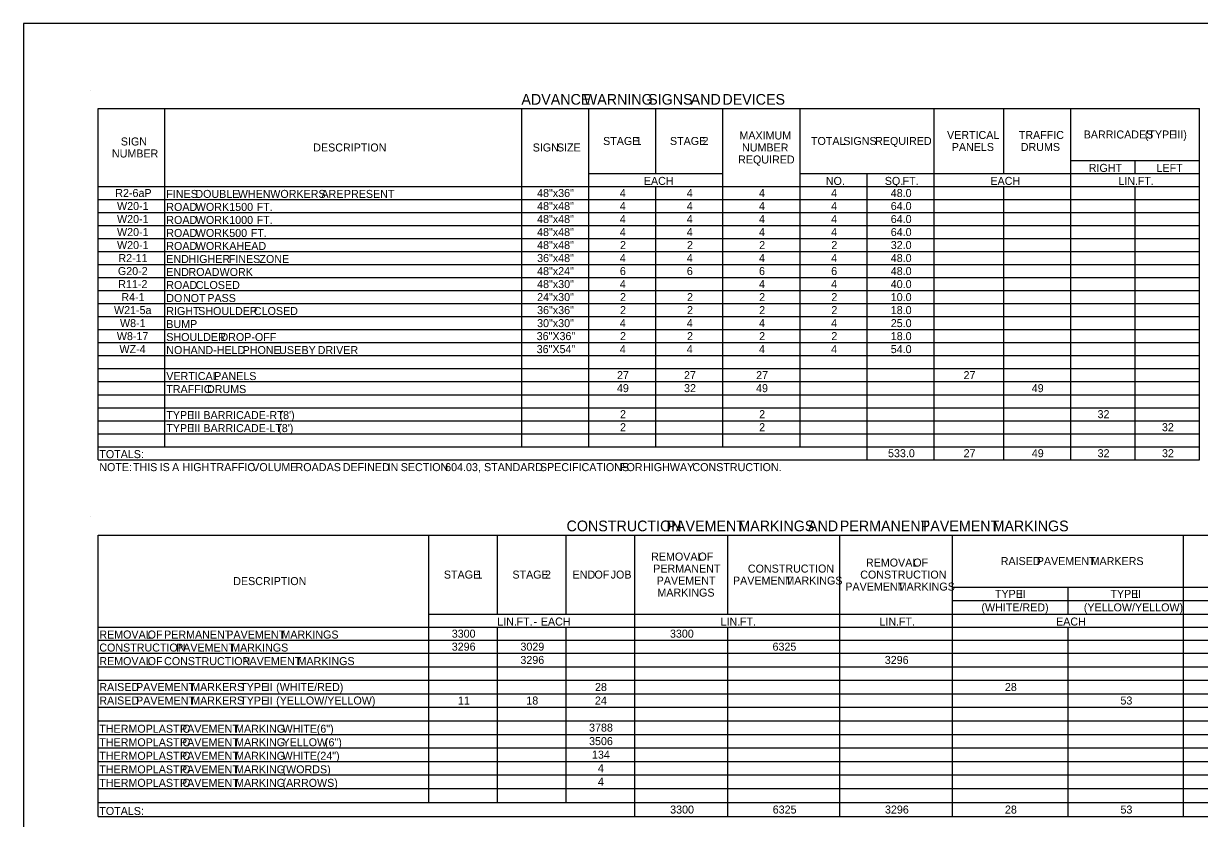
# Model space of a CAD drawing. Extents: x 3289 to 10164, y -1238 to -188.
# Drawn here: x 3289 to 4170, y -784 to -188 of the extents above; entities that cross this region are included whole.
import ezdxf

# ---------------------------------------------------------------- set-up
doc = ezdxf.new("R2010")
doc.units = 0
for name, color, linetype in [('Default', 7, 'Continuous'), ('DSN_DRFT_Named-Boundary', 7, 'Continuous'), ('DSN_QNTY_Annotation', 7, 'Continuous')]:
    doc.layers.add(name, color=color, linetype=linetype)

msp = doc.modelspace()

# ---------------------------------------------------------------- linework, layer by layer
at = {"layer": 'DSN_DRFT_Named-Boundary'}
for p, q in [((3338.57, -237.74), (3338.57, -237.74)), ((3338.57, -557.44), (3338.57, -557.44))]:
    msp.add_line(p, q, dxfattribs=at)
msp.add_lwpolyline([(3288.57, -1237.74), (4913.57, -1237.74), (4913.57, -187.74), (3288.57, -187.74)], close=True, dxfattribs=at)
at = {"layer": 'DSN_QNTY_Annotation'}
for p, q in [((3344.42, -251.39), (4170.25, -251.39)), ((3344.42, -514.64), (3344.42, -251.39)), ((3344.42, -514.64), (3344.42, -251.39)), ((3394.63, -504.89), (3394.63, -251.39)), ((3662.27, -504.89), (3662.27, -251.39)), ((3712.48, -504.89), (3712.48, -251.39)), ((3762.7, -300.14), (3762.7, -251.39)), ((3812.91, -504.89), (3812.91, -251.39)), ((3870.92, -504.89), (3870.92, -251.39)), ((3971.35, -514.64), (3971.35, -251.39)), ((4023.51, -300.14), (4023.51, -251.39)), ((4073.72, -514.64), (4073.72, -251.39)), ((4170.25, -514.64), (4170.25, -251.39)), ((4170.25, -397.64), (4170.25, -251.39)), ((4073.72, -290.39), (4170.25, -290.39)), ((4121.98, -300.14), (4121.98, -290.39)), ((4121.98, -300.14), (4121.98, -290.39)), ((3712.48, -300.14), (3812.91, -300.14)), ((3812.91, -504.89), (3812.91, -300.14)), ((3870.92, -300.14), (4170.25, -300.14)), ((3921.13, -514.64), (3921.13, -300.14)), ((4073.72, -300.14), (4121.98, -300.14)), ((4073.72, -514.64), (4073.72, -300.14)), ((4121.98, -300.14), (4170.25, -300.14)), ((3344.42, -309.89), (4170.25, -309.89)), ((3394.63, -504.89), (3394.63, -309.89)), ((3712.48, -504.89), (3712.48, -309.89)), ((3762.7, -504.89), (3762.7, -309.89)), ((3762.7, -504.89), (3762.7, -309.89)), ((3812.91, -309.89), (4170.25, -309.89)), ((3921.13, -514.64), (3921.13, -309.89)), ((3971.35, -514.64), (3971.35, -309.89)), ((4023.51, -514.64), (4023.51, -309.89)), ((4023.51, -514.64), (4023.51, -309.89)), ((4121.98, -514.64), (4121.98, -309.89)), ((4121.98, -514.64), (4121.98, -309.89)), ((3344.42, -319.64), (4170.25, -319.64)), ((3662.27, -504.89), (3662.27, -319.64)), ((3344.42, -329.39), (4170.25, -329.39)), ((3344.42, -339.14), (4170.25, -339.14)), ((3344.42, -348.89), (4170.25, -348.89)), ((3344.42, -358.64), (4170.25, -358.64)), ((3344.42, -368.39), (4170.25, -368.39)), ((3344.42, -378.14), (4170.25, -378.14)), ((3344.42, -387.89), (4170.25, -387.89)), ((3344.42, -397.64), (4170.25, -397.64)), ((3344.42, -407.39), (4170.25, -407.39)), ((4170.25, -514.64), (4170.25, -407.39)), ((3344.42, -417.14), (4170.25, -417.14)), ((3344.42, -426.89), (4170.25, -426.89)), ((3344.42, -436.64), (4170.25, -436.64)), ((3344.42, -446.39), (4170.25, -446.39)), ((3344.42, -456.14), (4170.25, -456.14)), ((3344.42, -465.89), (4170.25, -465.89)), ((3344.42, -475.64), (4170.25, -475.64)), ((3344.42, -485.39), (4170.25, -485.39)), ((3344.42, -495.14), (4170.25, -495.14)), ((3344.42, -504.89), (4170.25, -504.89)), ((3344.42, -514.64), (4170.25, -514.64)), ((3344.42, -571.09), (4415.75, -571.09)), ((3344.42, -782.08), (3344.42, -571.09)), ((3344.42, -782.08), (3344.42, -571.09)), ((3592.46, -771.55), (3592.46, -571.09)), ((3643.94, -630.37), (3643.94, -571.09)), ((3695.42, -630.37), (3695.42, -571.09)), ((3746.9, -782.08), (3746.9, -571.09)), ((3816.71, -630.37), (3816.71, -571.09)), ((3900.56, -782.08), (3900.56, -571.09)), ((3985.19, -782.08), (3985.19, -571.09)), ((4158.35, -782.08), (4158.35, -571.09)), ((3985.19, -610.09), (4415.75, -610.09)), ((4071.77, -630.37), (4071.77, -610.09)), ((3985.19, -620.23), (4312.79, -620.23)), ((3592.46, -630.37), (4415.75, -630.37)), ((3985.19, -782.08), (3985.19, -630.37)), ((3344.42, -640.12), (4415.75, -640.12)), ((3592.46, -771.55), (3592.46, -640.12)), ((3643.94, -771.55), (3643.94, -640.12)), ((3643.94, -771.55), (3643.94, -640.12)), ((3695.42, -771.55), (3695.42, -640.12)), ((3695.42, -771.55), (3695.42, -640.12)), ((3746.9, -782.08), (3746.9, -640.12)), ((3816.71, -782.08), (3816.71, -640.12)), ((3816.71, -782.08), (3816.71, -640.12)), ((3900.56, -782.08), (3900.56, -640.12)), ((4071.77, -782.08), (4071.77, -640.12)), ((4071.77, -782.08), (4071.77, -640.12)), ((4158.35, -782.08), (4158.35, -640.12)), ((3344.42, -649.87), (4415.75, -649.87)), ((3344.42, -659.62), (4415.75, -659.62)), ((3344.42, -669.76), (4415.75, -669.76)), ((3344.42, -679.9), (4415.75, -679.9)), ((3344.42, -690.04), (4415.75, -690.04)), ((3344.42, -700.18), (4415.75, -700.18)), ((3344.42, -710.32), (4415.75, -710.32)), ((3344.42, -720.46), (4415.75, -720.46)), ((3344.42, -730.6), (4415.75, -730.6)), ((3344.42, -740.74), (4415.75, -740.74)), ((3344.42, -750.88), (4415.75, -750.88)), ((3344.42, -761.02), (4415.75, -761.02)), ((3344.42, -771.55), (4415.75, -771.55)), ((3344.42, -782.08), (4415.75, -782.08))]:
    msp.add_line(p, q, dxfattribs=at)

# ---------------------------------------------------------------- texts
at = {"layer": 'Default'}
for s, height, p in [('ADVANCE', 8, (3661.86, -248.56)), (' WARNING', 8, (3705.63, -248.56)), (' SIGNS', 8, (3753.95, -248.56)), (' AND', 8, (3785.79, -248.56)), (' DEVICES', 8, (3809.58, -248.56)), ('SIGN', 6, (3361.54, -279.14)), ('STAGE', 6, (3723.11, -278.76)), (' 1', 6, (3745.31, -278.76)), ('STAGE', 6, (3773.24, -278.76)), (' 2', 6, (3795.44, -278.76)), ('MAXIMUM', 6, (3825.33, -274.64)), ('TOTAL', 6, (3878.96, -278.76)), (' SIGNS', 6, (3900.97, -278.76)), (' REQUIRED', 6, (3924.85, -278.76)), ('VERTICAL', 6, (3980.97, -274.26)), ('TRAFFIC', 6, (4034.77, -274.26)), ('BARRICADES', 6, (4083.45, -273.89)), (' (TYPE', 6, (4127.02, -273.89)), (' III)', 6, (4149.21, -273.89)), ('DESCRIPTION', 6, (3505.81, -283.64)), ('SIGN', 6, (3670.34, -283.64)), (' SIZE', 6, (3686.3, -283.64)), ('NUMBER', 6, (3827.26, -283.64)), ('PANELS', 6, (3984.52, -283.26)), ('DRUMS', 6, (4036.27, -283.26)), ('NUMBER', 6, (3354.87, -288.14)), ('REQUIRED', 6, (3824.34, -292.64)), ('RIGHT', 6, (4087.23, -298.94)), ('LEFT', 6, (4138.05, -298.94)), ('EACH', 6, (3753.65, -308.69)), ('NO.', 6, (3890.11, -308.69)), ('SQ.', 6, (3934.32, -308.69)), (' FT.', 6, (3945.38, -308.69)), ('EACH', 6, (4013.49, -308.69)), ('LIN.', 6, (4109.46, -308.69)), (' FT.', 6, (4121.73, -308.69)), ('R2-6aP', 6, (3357.36, -317.76)), ('FINES', 6, (3395.61, -318.44)), (' DOUBLE', 6, (3415.19, -318.44)), (' WHEN', 6, (3447.04, -318.44)), (' WORKERS', 6, (3471.36, -318.44)), (' ARE', 6, (3509.72, -318.44)), (' PRESENT', 6, (3526.53, -318.44)), ('48"x36"', 6, (3673.64, -317.76)), ('4', 6, (3735.65, -317.76)), ('4', 6, (3785.86, -317.76)), ('4', 6, (3839.98, -317.76)), ('4', 6, (3894.09, -317.76)), ('48.0', 6, (3938.79, -317.76)), ('W20-1', 6, (3358.68, -327.51)), ('ROAD', 6, (3395.61, -328.19)), (' WORK', 6, (3415.52, -328.19)), (' 1500', 6, (3440.6, -328.19)), (' FT.', 6, (3461.13, -328.19)), ('48"x48"', 6, (3673.64, -327.51)), ('4', 6, (3735.65, -327.51)), ('4', 6, (3785.86, -327.51)), ('4', 6, (3839.98, -327.51)), ('4', 6, (3894.09, -327.51)), ('64.0', 6, (3938.79, -327.51)), ('W20-1', 6, (3358.68, -337.26)), ('ROAD', 6, (3395.61, -337.94)), (' WORK', 6, (3415.52, -337.94)), (' 1000', 6, (3440.6, -337.94)), (' FT.', 6, (3461.13, -337.94)), ('48"x48"', 6, (3673.64, -337.26)), ('4', 6, (3735.65, -337.26)), ('4', 6, (3785.86, -337.26)), ('4', 6, (3839.98, -337.26)), ('4', 6, (3894.09, -337.26)), ('64.0', 6, (3938.79, -337.26)), ('W20-1', 6, (3358.68, -347.01)), ('ROAD', 6, (3395.61, -347.69)), (' WORK', 6, (3415.52, -347.69)), (' 500', 6, (3440.6, -347.69)), (' FT.', 6, (3456.69, -347.69)), ('48"x48"', 6, (3673.64, -347.01)), ('4', 6, (3735.65, -347.01)), ('4', 6, (3785.86, -347.01)), ('4', 6, (3839.98, -347.01)), ('4', 6, (3894.09, -347.01)), ('64.0', 6, (3938.79, -347.01)), ('W20-1', 6, (3358.68, -356.76)), ('ROAD', 6, (3395.61, -357.44)), (' WORK', 6, (3415.52, -357.44)), (' AHEAD', 6, (3440.6, -357.44)), ('48"x48"', 6, (3673.64, -356.76)), ('2', 6, (3735.8, -356.76)), ('2', 6, (3786.02, -356.76)), ('2', 6, (3840.13, -356.76)), ('2', 6, (3894.24, -356.76)), ('32.0', 6, (3938.79, -356.76)), ('R2-11', 6, (3359.71, -366.51)), ('END', 6, (3395.61, -367.19)), (' HIGHER', 6, (3410.03, -367.19)), (' FINES', 6, (3440.24, -367.19)), (' ZONE', 6, (3463.22, -367.19)), ('36"x48"', 6, (3673.64, -366.51)), ('4', 6, (3735.65, -366.51)), ('4', 6, (3785.86, -366.51)), ('4', 6, (3839.98, -366.51)), ('4', 6, (3894.09, -366.51)), ('48.0', 6, (3938.79, -366.51)), ('G20-2', 6, (3359.34, -376.26)), ('48"x24"', 6, (3673.64, -376.26)), ('6', 6, (3735.68, -376.26)), ('6', 6, (3785.89, -376.26)), ('6', 6, (3840, -376.26)), ('6', 6, (3894.11, -376.26)), ('48.0', 6, (3938.79, -376.26)), ('END', 6, (3395.61, -376.94)), (' ROAD', 6, (3410.03, -376.94)), (' WORK', 6, (3433.35, -376.94)), ('R11-2', 6, (3359.62, -386.01)), ('ROAD', 6, (3395.61, -386.69)), (' CLOSED', 6, (3415.52, -386.69)), ('48"x30"', 6, (3673.64, -386.01)), ('4', 6, (3735.65, -386.01)), ('4', 6, (3839.98, -386.01)), ('4', 6, (3894.09, -386.01)), ('40.0', 6, (3938.79, -386.01)), ('R4-1', 6, (3361.93, -395.76)), ('DO', 6, (3395.61, -396.44)), (' NOT', 6, (3405.91, -396.44)), (' PASS', 6, (3424.15, -396.44)), ('24"x30"', 6, (3673.64, -395.76)), ('2', 6, (3735.8, -395.76)), ('2', 6, (3786.02, -395.76)), ('2', 6, (3840.13, -395.76)), ('2', 6, (3894.24, -395.76)), ('10.0', 6, (3938.79, -395.76)), ('W21-5a', 6, (3356.42, -405.51)), ('RIGHT', 6, (3395.61, -406.19)), (' SHOULDER', 6, (3417.29, -406.19)), (' CLOSED', 6, (3459.07, -406.19)), ('36"x36"', 6, (3673.64, -405.51)), ('2', 6, (3735.8, -405.51)), ('2', 6, (3786.02, -405.51)), ('2', 6, (3840.13, -405.51)), ('2', 6, (3894.24, -405.51)), ('18.0', 6, (3938.79, -405.51)), ('W8-1', 6, (3360.9, -415.26)), ('BUMP', 6, (3395.61, -415.94)), ('30"x30"', 6, (3673.64, -415.26)), ('4', 6, (3735.65, -415.26)), ('4', 6, (3785.86, -415.26)), ('4', 6, (3839.98, -415.26)), ('4', 6, (3894.09, -415.26)), ('25.0', 6, (3938.79, -415.26)), ('W8-17', 6, (3358.54, -425.01)), ('SHOULDER', 6, (3395.61, -425.69)), (' DROP-OFF', 6, (3433.99, -425.69)), ('36"X36"', 6, (3673.32, -425.01)), ('2', 6, (3735.8, -425.01)), ('2', 6, (3786.02, -425.01)), ('2', 6, (3840.13, -425.01)), ('2', 6, (3894.24, -425.01)), ('18.0', 6, (3938.79, -425.01)), ('WZ-4', 6, (3360.49, -434.76)), ('NO', 6, (3395.61, -435.44)), (' HAND-HELD', 6, (3405.76, -435.44)), (' PHONE', 6, (3450.64, -435.44)), (' USE', 6, (3478.02, -435.44)), (' BY', 6, (3494.75, -435.44)), (' DRIVER', 6, (3506.9, -435.44)), ('36"X54"', 6, (3673.32, -434.76)), ('4', 6, (3735.65, -434.76)), ('4', 6, (3785.86, -434.76)), ('4', 6, (3839.98, -434.76)), ('4', 6, (3894.09, -434.76)), ('54.0', 6, (3938.79, -434.76)), ('VERTICAL', 6, (3395.61, -454.94)), (' PANELS', 6, (3429.29, -454.94)), ('27', 6, (3733.53, -454.26)), ('27', 6, (3783.74, -454.26)), ('27', 6, (3837.86, -454.26)), ('27', 6, (3993.37, -454.26)), ('49', 6, (3733.48, -464.01)), ('32', 6, (3783.8, -464.01)), ('49', 6, (3837.8, -464.01)), ('49', 6, (4044.5, -464.01)), ('TRAFFIC', 6, (3395.61, -464.69)), (' DRUMS', 6, (3423.91, -464.69)), ('TYPE', 6, (3395.61, -484.19)), (' III', 6, (3412.14, -484.19)), (' BARRICADE-RT.', 6, (3421.2, -484.19)), (" (8')", 6, (3478.28, -484.19)), ('2', 6, (3735.8, -483.51)), ('2', 6, (3840.13, -483.51)), ('32', 6, (4093.85, -483.51)), ('TYPE', 6, (3395.61, -493.94)), (' III', 6, (3412.14, -493.94)), (' BARRICADE-LT.', 6, (3421.2, -493.94)), (" (8')", 6, (3477.32, -493.94)), ('2', 6, (3735.8, -493.26)), ('2', 6, (3840.13, -493.26)), ('32', 6, (4142.11, -493.26)), ('TOTALS:', 6, (3345.4, -513.44)), ('533.0', 6, (3936.75, -512.76)), ('27', 6, (3993.41, -512.76)), ('49', 6, (4044.54, -512.76)), ('32', 6, (4093.88, -512.76)), ('32', 6, (4142.15, -512.76)), ('NOTE:', 6, (3345.4, -523.19)), ('  THIS', 6, (3366.15, -523.19)), (' IS', 6, (3388.4, -523.19)), (' A', 6, (3397.73, -523.19)), (' HIGH', 6, (3405.6, -523.19)), (' TRAFFIC', 6, (3426.11, -523.19)), (' VOLUME', 6, (3457.82, -523.19)), (' ROAD', 6, (3490.3, -523.19)), (' AS', 6, (3513.62, -523.19)), (' DEFINED', 6, (3525.66, -523.19)), (' IN', 6, (3559.35, -523.19)), (' SECTION', 6, (3569.17, -523.19)), (' 604.03,', 6, (3602.47, -523.19)), (' STANDARD', 6, (3631.63, -523.19)), (' SPECIFICATIONS', 6, (3673.51, -523.19)), (' FOR', 6, (3733.53, -523.19)), (' HIGHWAY', 6, (3750.87, -523.19)), (' CONSTRUCTION.', 6, (3787.87, -523.19)), ('CONSTRUCTION', 8, (3695.72, -568.26)), (' PAVEMENT', 8, (3767.66, -568.26)), (' MARKINGS', 8, (3821.48, -568.26)), (' AND', 8, (3873.81, -568.26)), (' PERMANENT', 8, (3897.6, -568.26)), (' PAVEMENT', 8, (3958.3, -568.26)), (' MARKINGS', 8, (4012.12, -568.26)), ('REMOVAL', 6, (3759.12, -590.23)), (' OF', 6, (3792.35, -590.23)), ('REMOVAL', 6, (3920.19, -594.73)), (' OF', 6, (3953.42, -594.73)), ('RAISED', 6, (4021.24, -593.59)), (' PAVEMENT', 6, (4046.02, -593.59)), (' MARKERS', 6, (4086.39, -593.59)), ('STAGE', 6, (3603.72, -603.73)), (' 1', 6, (3625.93, -603.73)), ('STAGE', 6, (3655.12, -603.73)), (' 2', 6, (3677.32, -603.73)), ('END', 6, (3700.24, -603.73)), (' OF', 6, (3714.42, -603.73)), (' JOB', 6, (3726.56, -603.73)), ('PERMANENT', 6, (3760.7, -599.23)), ('CONSTRUCTION', 6, (3831.66, -599.23)), ('CONSTRUCTION', 6, (3915.9, -603.73)), ('DESCRIPTION', 6, (3445.8, -608.6)), ('PAVEMENT', 6, (3763.28, -608.23)), ('PAVEMENT', 6, (3820.48, -608.23)), (' MARKINGS', 6, (3857.54, -608.23)), ('PAVEMENT', 6, (3904.72, -612.73)), (' MARKINGS', 6, (3941.78, -612.73)), ('MARKINGS', 6, (3763.84, -617.23)), ('TYPE', 6, (4016.89, -618.16)), (' II', 6, (4033.12, -618.16)), ('TYPE', 6, (4103.47, -618.16)), (' II', 6, (4119.7, -618.16)), ('(WHITE/RED)', 6, (4006.76, -628.3)), ('(YELLOW/YELLOW)', 6, (4083.53, -628.3)), ('LIN.', 6, (3643.75, -638.92)), (' FT.', 6, (3656.03, -638.92)), (' EACH', 6, (3674.2, -638.92)), ('LIN.', 6, (3811.21, -638.92)), (' FT.', 6, (3823.48, -638.92)), ('LIN.', 6, (3930.35, -638.92)), (' FT.', 6, (3942.63, -638.92)), ('EACH', 6, (4062.72, -638.92)), ('REMOVAL', 6, (3345.4, -648.67)), (' OF', 6, (3379.4, -648.67)), (' PERMANENT', 6, (3391.74, -648.67)), (' PAVEMENT', 6, (3438.38, -648.67)), (' MARKINGS', 6, (3479.71, -648.67)), ('3300', 6, (3609.64, -647.99)), (' -', 6, (3668.8, -638.92)), ('3300', 6, (3773.24, -647.99)), ('CONSTRUCTION', 6, (3345.4, -658.42)), (' PAVEMENT', 6, (3400.69, -658.42)), (' MARKINGS', 6, (3442.03, -658.42)), ('3296', 6, (3609.63, -657.74)), ('3029', 6, (3661.13, -657.74)), ('6325', 6, (3850.15, -657.74)), ('REMOVAL', 6, (3345.4, -668.56)), (' OF', 6, (3379.4, -668.56)), (' CONSTRUCTION', 6, (3391.74, -668.56)), (' PAVEMENT', 6, (3450.44, -668.56)), (' MARKINGS', 6, (3491.78, -668.56)), ('3296', 6, (3661.11, -667.69)), ('3296', 6, (3934.3, -667.69)), ('RAISED', 6, (3345.4, -687.97)), (' PAVEMENT', 6, (3370.71, -687.97)), (' MARKERS', 6, (3412.05, -687.97)), (' TYPE', 6, (3448.81, -687.97)), (' II', 6, (3468.73, -687.97)), (' (WHITE/RED)', 6, (3475.74, -687.97)), ('28', 6, (3717.04, -687.97)), ('28', 6, (4024.36, -687.97)), ('RAISED', 6, (3345.4, -698.11)), (' PAVEMENT', 6, (3370.71, -698.11)), (' MARKERS', 6, (3412.05, -698.11)), (' TYPE', 6, (3448.81, -698.11)), (' II', 6, (3468.73, -698.11)), (' (YELLOW/YELLOW)', 6, (3475.74, -698.11)), ('11', 6, (3614.28, -698.11)), ('18', 6, (3665.56, -698.11)), ('24', 6, (3717, -698.11)), ('53', 6, (4110.99, -698.11)), ('THERMOPLASTIC', 6, (3345.4, -719.26)), (' PAVEMENT', 6, (3403.64, -719.26)), (' MARKING', 6, (3444.98, -719.26)), (' WHITE', 6, (3480.55, -719.26)), (' (6")', 6, (3506.21, -719.26)), ('3788', 6, (3712.6, -718.39)), ('3506', 6, (3712.59, -728.53)), ('THERMOPLASTIC', 6, (3345.4, -729.4)), (' PAVEMENT', 6, (3403.64, -729.4)), (' MARKING', 6, (3444.98, -729.4)), (' YELLOW', 6, (3480.55, -729.4)), (' (6")', 6, (3512.35, -729.4)), ('THERMOPLASTIC', 6, (3345.4, -739.54)), (' PAVEMENT', 6, (3403.64, -739.54)), (' MARKING', 6, (3444.98, -739.54)), (' WHITE', 6, (3480.55, -739.54)), (' (24")', 6, (3506.21, -739.54)), ('134', 6, (3714.78, -738.67)), ('THERMOPLASTIC', 6, (3345.4, -749.68)), (' PAVEMENT', 6, (3403.64, -749.68)), (' MARKING', 6, (3444.98, -749.68)), (' (WORDS)', 6, (3480.55, -749.68)), ('4', 6, (3719.22, -748.81)), ('THERMOPLASTIC', 6, (3345.4, -759.82)), (' PAVEMENT', 6, (3403.64, -759.82)), (' MARKING', 6, (3444.98, -759.82)), (' (ARROWS)', 6, (3480.55, -759.82)), ('4', 6, (3719.22, -758.95)), ('TOTALS:', 6, (3345.4, -780.88)), ('3300', 6, (3773.4, -779.81)), ('6325', 6, (3850.3, -779.81)), ('3296', 6, (3934.46, -779.81)), ('28', 6, (4024.4, -779.81)), ('53', 6, (4111.02, -779.81))]:
    msp.add_text(s, height=height, dxfattribs=at).set_placement(p)

doc.saveas('drawing.dxf')
